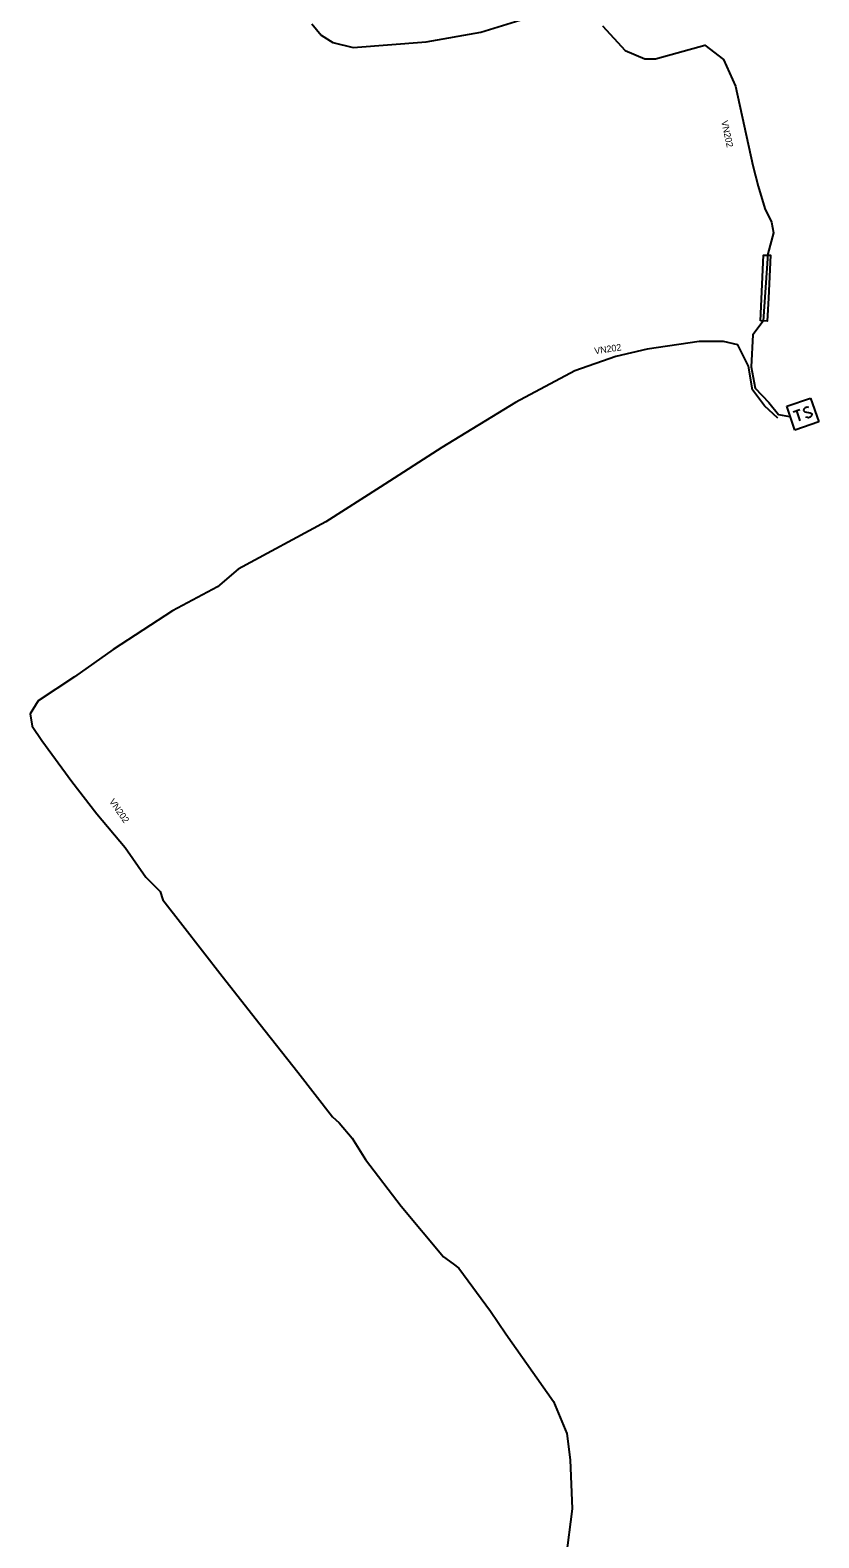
# Model space of a CAD drawing. Extents: x -643811 to -636362, y -1117362 to -1108614.
# Drawn here: x -642279.3 to -642161.2, y -1114758.6 to -1114532.9 of the extents above; entities that cross this region are included whole.
import ezdxf

# ---------------------------------------------------------------- set-up
doc = ezdxf.new("R2010")
doc.units = 0
for name, color, linetype in [('20', 7, 'Continuous'), ('25', 7, 'Continuous'), ('5', 7, 'Continuous'), ('7', 7, 'Continuous')]:
    doc.layers.add(name, color=color, linetype=linetype)

# ---------------------------------------------------------------- blocks, each defined once
blk = doc.blocks.new('VN640')
at = {"layer": '25'}
for points in [[(-1.89, 1.89), (1.89, 1.89)], [(-1.89, -1.89), (-1.89, 1.89)], [(-1.26, 0.79), (-0.22, 0.79)], [(-0.73, 0.79), (-0.73, -0.79)], [(1.2, 0.66), (0.94, 0.79), (0.66, 0.79), (0.41, 0.66), (0.28, 0.47), (0.28, 0.41), (0.41, 0.22), (1.13, -0.16), (1.26, -0.32), (1.26, -0.47), (1.13, -0.66), (0.91, -0.79), (0.63, -0.79), (0.5, -0.73), (0.28, -0.6)], [(1.89, 1.89), (1.89, -1.89)], [(1.89, -1.89), (-1.89, -1.89)]]:
    blk.add_lwpolyline(points, dxfattribs=at)

msp = doc.modelspace()

# ---------------------------------------------------------------- linework, layer by layer
at = {"layer": '20'}
msp.add_lwpolyline([(-642169.95, -1114576.47), (-642169.48, -1114566.61), (-642169.02, -1114566.63), (-642168.48, -1114566.65), (-642168.78, -1114573.08), (-642168.95, -1114576.51)], close=True, dxfattribs=at)
at = {"layer": '5'}
for points in [[(-642237.1, -1114532), (-642235.7, -1114533.68), (-642233.94, -1114534.79), (-642230.9, -1114535.53), (-642219.99, -1114534.72), (-642211.8, -1114533.25), (-642205.32, -1114531.28)], [(-642193.62, -1114532.32), (-642190.22, -1114536.01), (-642187.26, -1114537.22), (-642185.66, -1114537.24), (-642178.3, -1114535.22), (-642175.47, -1114537.32), (-642173.72, -1114541.33), (-642171.12, -1114553.21), (-642170.28, -1114556.3), (-642169.3, -1114559.62), (-642168.33, -1114561.69), (-642168.02, -1114563.31), (-642168.85, -1114566.41), (-642169.54, -1114576.5), (-642171.09, -1114578.53), (-642171.33, -1114583.33), (-642170.73, -1114586.54), (-642168.7, -1114588.66), (-642167.24, -1114590.5), (-642165.6, -1114590.77)], [(-642167.35, -1114591.04), (-642169.36, -1114589.18), (-642171.16, -1114586.77), (-642171.75, -1114583.26), (-642173.37, -1114580.07), (-642175.49, -1114579.57), (-642179.13, -1114579.55), (-642186.94, -1114580.69), (-642191.61, -1114581.82), (-642197.74, -1114583.93), (-642206.62, -1114588.7), (-642217.66, -1114595.43), (-642226.86, -1114601.33), (-642235.02, -1114606.52), (-642248.13, -1114613.65), (-642251.2, -1114616.27), (-642257.95, -1114619.85), (-642266.83, -1114625.63), (-642272.63, -1114629.75), (-642278.07, -1114633.35), (-642279.26, -1114635.26), (-642278.95, -1114637.14), (-642277.5, -1114639.27), (-642273.04, -1114645.43), (-642269.3, -1114650.25), (-642265.04, -1114655.31), (-642261.95, -1114659.74), (-642259.79, -1114661.86), (-642259.39, -1114663.1), (-642256.42, -1114666.94), (-642250.52, -1114674.56), (-642244.82, -1114681.76), (-642239.21, -1114688.93), (-642234, -1114695.6), (-642233.03, -1114696.5), (-642231.05, -1114698.81), (-642229.07, -1114701.97), (-642223.72, -1114708.95), (-642217.42, -1114716.55), (-642215.97, -1114717.58), (-642215.12, -1114718.24), (-642210.35, -1114724.7), (-642208.06, -1114728.06), (-642200.95, -1114738.23), (-642198.92, -1114742.98), (-642198.42, -1114746.92), (-642198.13, -1114754.29), (-642199.09, -1114761.64)]]:
    msp.add_lwpolyline(points, dxfattribs=at)

# ---------------------------------------------------------------- block references
at = {"layer": '25', "rotation": 18.999999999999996}
msp.add_blockref('VN640', (-642163.62, -1114590.42), dxfattribs=at)

# ---------------------------------------------------------------- texts
at = {"layer": '7'}
for rotation, p in [(282.3412, (-642175.84, -1114546.6)), (8.2964, (-642194.75, -1114581.46)), (304.9201, (-642267.5, -1114648.41))]:
    msp.add_text('VN202', height=0.994, rotation=rotation, dxfattribs=at).set_placement(p)

doc.saveas('drawing.dxf')
